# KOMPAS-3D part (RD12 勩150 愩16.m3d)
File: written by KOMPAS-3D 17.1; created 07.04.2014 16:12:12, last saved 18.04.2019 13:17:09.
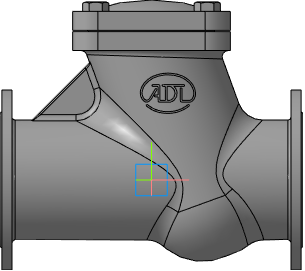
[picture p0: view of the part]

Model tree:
1. Операция без истории:2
